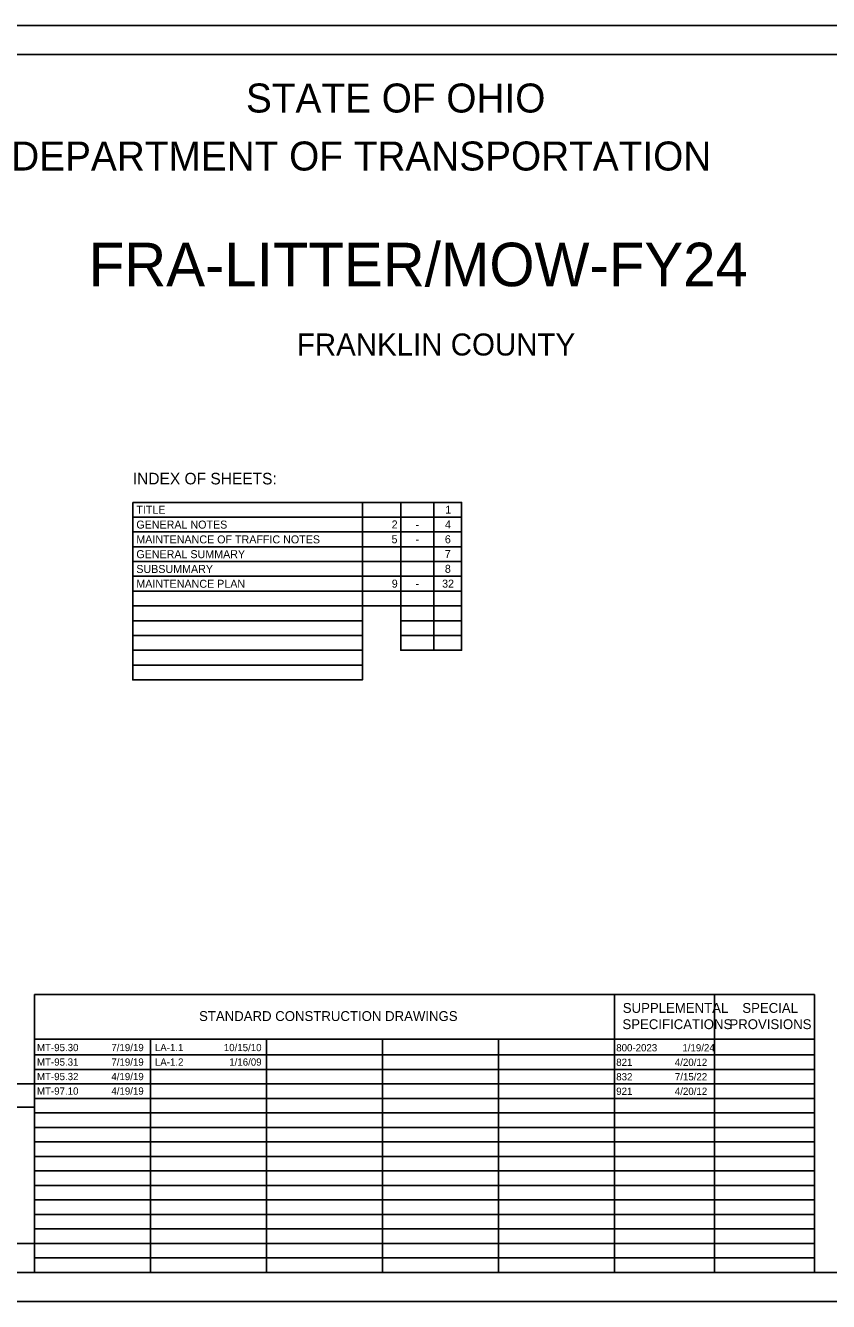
# Model space of a CAD drawing. Extents: x -7.1 to 34, y 0 to 22.
# Drawn here: x 9.99 to 23.84, y 0 to 22 of the extents above; entities that cross this region are included whole.
import ezdxf

# ---------------------------------------------------------------- set-up
doc = ezdxf.new("R2010")
doc.units = 0
for name, color, linetype in [('Default', 7, 'Continuous'), ('SH_Border', 7, 'Continuous'), ('SH_Cut_Line', 7, 'Continuous'), ('SH_Data', 7, 'Continuous'), ('SH_Text', 7, 'Continuous')]:
    doc.layers.add(name, color=color, linetype=linetype)

msp = doc.modelspace()

# ---------------------------------------------------------------- linework, layer by layer
at = {"layer": 'Default'}
for points in [[(11.844, 13.778), (15.804, 13.778), (15.804, 13.523), (11.844, 13.523)], [(15.804, 13.778), (16.464, 13.778), (16.464, 13.523), (15.804, 13.523)], [(16.464, 13.778), (17.034, 13.778), (17.034, 13.523), (16.464, 13.523)], [(17.034, 13.778), (17.514, 13.778), (17.514, 13.523), (17.034, 13.523)], [(11.844, 13.523), (15.804, 13.523), (15.804, 13.268), (11.844, 13.268)], [(15.804, 13.523), (16.464, 13.523), (16.464, 13.268), (15.804, 13.268)], [(16.464, 13.523), (17.034, 13.523), (17.034, 13.268), (16.464, 13.268)], [(17.034, 13.523), (17.514, 13.523), (17.514, 13.268), (17.034, 13.268)], [(11.844, 13.268), (15.804, 13.268), (15.804, 13.013), (11.844, 13.013)], [(15.804, 13.268), (16.464, 13.268), (16.464, 13.013), (15.804, 13.013)], [(16.464, 13.268), (17.034, 13.268), (17.034, 13.013), (16.464, 13.013)], [(17.034, 13.268), (17.514, 13.268), (17.514, 13.013), (17.034, 13.013)], [(11.844, 13.013), (15.804, 13.013), (15.804, 12.758), (11.844, 12.758)], [(15.804, 13.013), (16.464, 13.013), (16.464, 12.758), (15.804, 12.758)], [(16.464, 13.013), (17.034, 13.013), (17.034, 12.758), (16.464, 12.758)], [(17.034, 13.013), (17.514, 13.013), (17.514, 12.758), (17.034, 12.758)], [(11.844, 12.758), (15.804, 12.758), (15.804, 12.503), (11.844, 12.503)], [(15.804, 12.758), (16.464, 12.758), (16.464, 12.503), (15.804, 12.503)], [(16.464, 12.758), (17.034, 12.758), (17.034, 12.503), (16.464, 12.503)], [(17.034, 12.758), (17.514, 12.758), (17.514, 12.503), (17.034, 12.503)], [(11.844, 12.503), (15.804, 12.503), (15.804, 12.248), (11.844, 12.248)], [(15.804, 12.503), (16.464, 12.503), (16.464, 12.248), (15.804, 12.248)], [(16.464, 12.503), (17.034, 12.503), (17.034, 12.248), (16.464, 12.248)], [(17.034, 12.503), (17.514, 12.503), (17.514, 12.248), (17.034, 12.248)], [(11.844, 12.248), (15.804, 12.248), (15.804, 11.993), (11.844, 11.993)], [(15.804, 12.248), (16.464, 12.248), (16.464, 11.993), (15.804, 11.993)], [(16.464, 12.248), (17.034, 12.248), (17.034, 11.993), (16.464, 11.993)], [(17.034, 12.248), (17.514, 12.248), (17.514, 11.993), (17.034, 11.993)], [(11.844, 11.993), (15.804, 11.993), (15.804, 11.738), (11.844, 11.738)], [(16.464, 11.993), (17.034, 11.993), (17.034, 11.738), (16.464, 11.738)], [(17.034, 11.993), (17.514, 11.993), (17.514, 11.738), (17.034, 11.738)], [(11.844, 11.738), (15.804, 11.738), (15.804, 11.483), (11.844, 11.483)], [(16.464, 11.738), (17.034, 11.738), (17.034, 11.483), (16.464, 11.483)], [(17.034, 11.738), (17.514, 11.738), (17.514, 11.483), (17.034, 11.483)], [(11.844, 11.483), (15.804, 11.483), (15.804, 11.228), (11.844, 11.228)], [(16.464, 11.483), (17.034, 11.483), (17.034, 11.228), (16.464, 11.228)], [(17.034, 11.483), (17.514, 11.483), (17.514, 11.228), (17.034, 11.228)], [(11.844, 11.228), (15.804, 11.228), (15.804, 10.973), (11.844, 10.973)], [(11.844, 10.973), (15.804, 10.973), (15.804, 10.718), (11.844, 10.718)]]:
    msp.add_lwpolyline(points, close=True, dxfattribs=at)
at = {"layer": 'SH_Border'}
msp.add_lwpolyline([(1.5, 21.5), (33.5, 21.5), (33.5, 0.5), (1.5, 0.5)], close=True, dxfattribs=at)
at = {"layer": 'SH_Cut_Line'}
msp.add_lwpolyline([(0, 0), (34, 0), (34, 22), (0, 22)], close=True, dxfattribs=at)
at = {"layer": 'SH_Data'}
for p, q in [((10.15, 5.292), (23.6, 5.292)), ((10.15, 0.5), (10.15, 5.292)), ((20.15, 0.5), (20.15, 5.292)), ((21.875, 0.5), (21.875, 5.292)), ((23.6, 0.5), (23.6, 5.292)), ((10.15, 4.521), (23.6, 4.521)), ((12.15, 0.5), (12.15, 4.521)), ((14.15, 0.5), (14.15, 4.521)), ((16.15, 0.5), (16.15, 4.521)), ((18.15, 0.5), (18.15, 4.521)), ((10.15, 4.25), (23.6, 4.25)), ((10.15, 4), (23.6, 4)), ((7.35, 3.75), (10.15, 3.75)), ((10.15, 3.75), (23.6, 3.75)), ((10.15, 3.75), (10.15, 0.5)), ((7.35, 3.35), (10.15, 3.35)), ((10.15, 3.5), (23.6, 3.5)), ((10.15, 3.25), (23.6, 3.25)), ((10.15, 3), (23.6, 3)), ((10.15, 2.75), (23.6, 2.75)), ((10.15, 2.5), (23.6, 2.5)), ((10.15, 2.25), (23.6, 2.25)), ((10.15, 2), (23.6, 2)), ((10.15, 1.75), (23.6, 1.75)), ((10.15, 1.5), (23.6, 1.5)), ((10.15, 1.25), (23.6, 1.25)), ((10.15, 1), (23.6, 1)), ((10.15, 0.75), (23.6, 0.75)), ((7.35, 0.5), (10.15, 0.5))]:
    msp.add_line(p, q, dxfattribs=at)
msp.add_lwpolyline([(7.35, 0.5), (7.35, 1), (10.15, 1), (10.15, 0.5)], close=True, dxfattribs=at)

# ---------------------------------------------------------------- texts
at = {"layer": 'Default'}
for s, p in [('TITLE', (11.904, 13.581)), ('1', (17.233, 13.583)), ('GENERAL NOTES', (11.904, 13.326)), ('2', (16.307, 13.328)), ('4', (17.227, 13.328)), ('MAINTENANCE OF TRAFFIC NOTES', (11.904, 13.071)), ('5', (16.305, 13.073)), ('-', (16.72, 13.328)), ('6', (17.225, 13.073)), ('-', (16.72, 13.073)), ('GENERAL SUMMARY', (11.904, 12.816)), ('7', (17.223, 12.818)), ('SUBSUMMARY', (11.904, 12.561)), ('8', (17.225, 12.563)), ('MAINTENANCE PLAN', (11.904, 12.306)), ('9', (16.309, 12.308)), ('-', (16.72, 12.308)), ('32', (17.177, 12.308))]:
    msp.add_text(s, height=0.138, dxfattribs=at).set_placement(p)
at = {"layer": 'SH_Text'}
for s, height, p in [('STATE OF OHIO', 0.5, (13.795, 20.5)), ('DEPARTMENT OF TRANSPORTATION', 0.5, (9.747, 19.5)), ('FRA-LITTER/MOW-FY24', 0.75, (11.083, 17.505)), ('FRANKLIN COUNTY', 0.38, (14.672, 16.31)), ('INDEX OF SHEETS:', 0.2, (11.844, 14.088)), ('SUPPLEMENTAL', 0.17, (20.293, 4.976)), ('SPECIAL', 0.17, (22.354, 4.976)), ('STANDARD CONSTRUCTION DRAWINGS', 0.17, (12.986, 4.836)), ('SPECIFICATIONS', 0.17, (20.287, 4.696)), ('PROVISIONS', 0.17, (22.132, 4.696)), ('MT-95.30', 0.125, (10.191, 4.316)), ('7/19/19', 0.125, (11.474, 4.316)), ('LA-1.1', 0.125, (12.224, 4.316)), ('10/15/10', 0.125, (13.413, 4.316)), ('800-2023', 0.125, (20.18, 4.312)), ('1/19/24', 0.125, (21.321, 4.312)), ('MT-95.31', 0.125, (10.191, 4.066)), ('7/19/19', 0.125, (11.474, 4.066)), ('LA-1.2', 0.125, (12.224, 4.066)), ('1/16/09', 0.125, (13.507, 4.066)), ('821', 0.125, (20.18, 4.062)), ('4/20/12', 0.125, (21.191, 4.062)), ('MT-95.32', 0.125, (10.191, 3.816)), ('4/19/19', 0.125, (11.474, 3.816)), ('832', 0.125, (20.18, 3.812)), ('7/15/22', 0.125, (21.191, 3.812)), ('MT-97.10', 0.125, (10.191, 3.566)), ('4/19/19', 0.125, (11.474, 3.566)), ('921', 0.125, (20.18, 3.562)), ('4/20/12', 0.125, (21.191, 3.562))]:
    msp.add_text(s, height=height, dxfattribs=at).set_placement(p)

doc.saveas('drawing.dxf')
